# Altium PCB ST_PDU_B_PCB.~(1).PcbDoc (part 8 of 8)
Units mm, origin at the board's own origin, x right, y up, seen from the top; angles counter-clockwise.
Board outline 200 x 200 mm, 6 copper layers (Top Layer, Layer 1, Layer 2, Layer 3, Layer 4, Bottom Layer), stack 3.194 mm thick; 894 components, 723 nets, 3233 pads, 4067 vias.
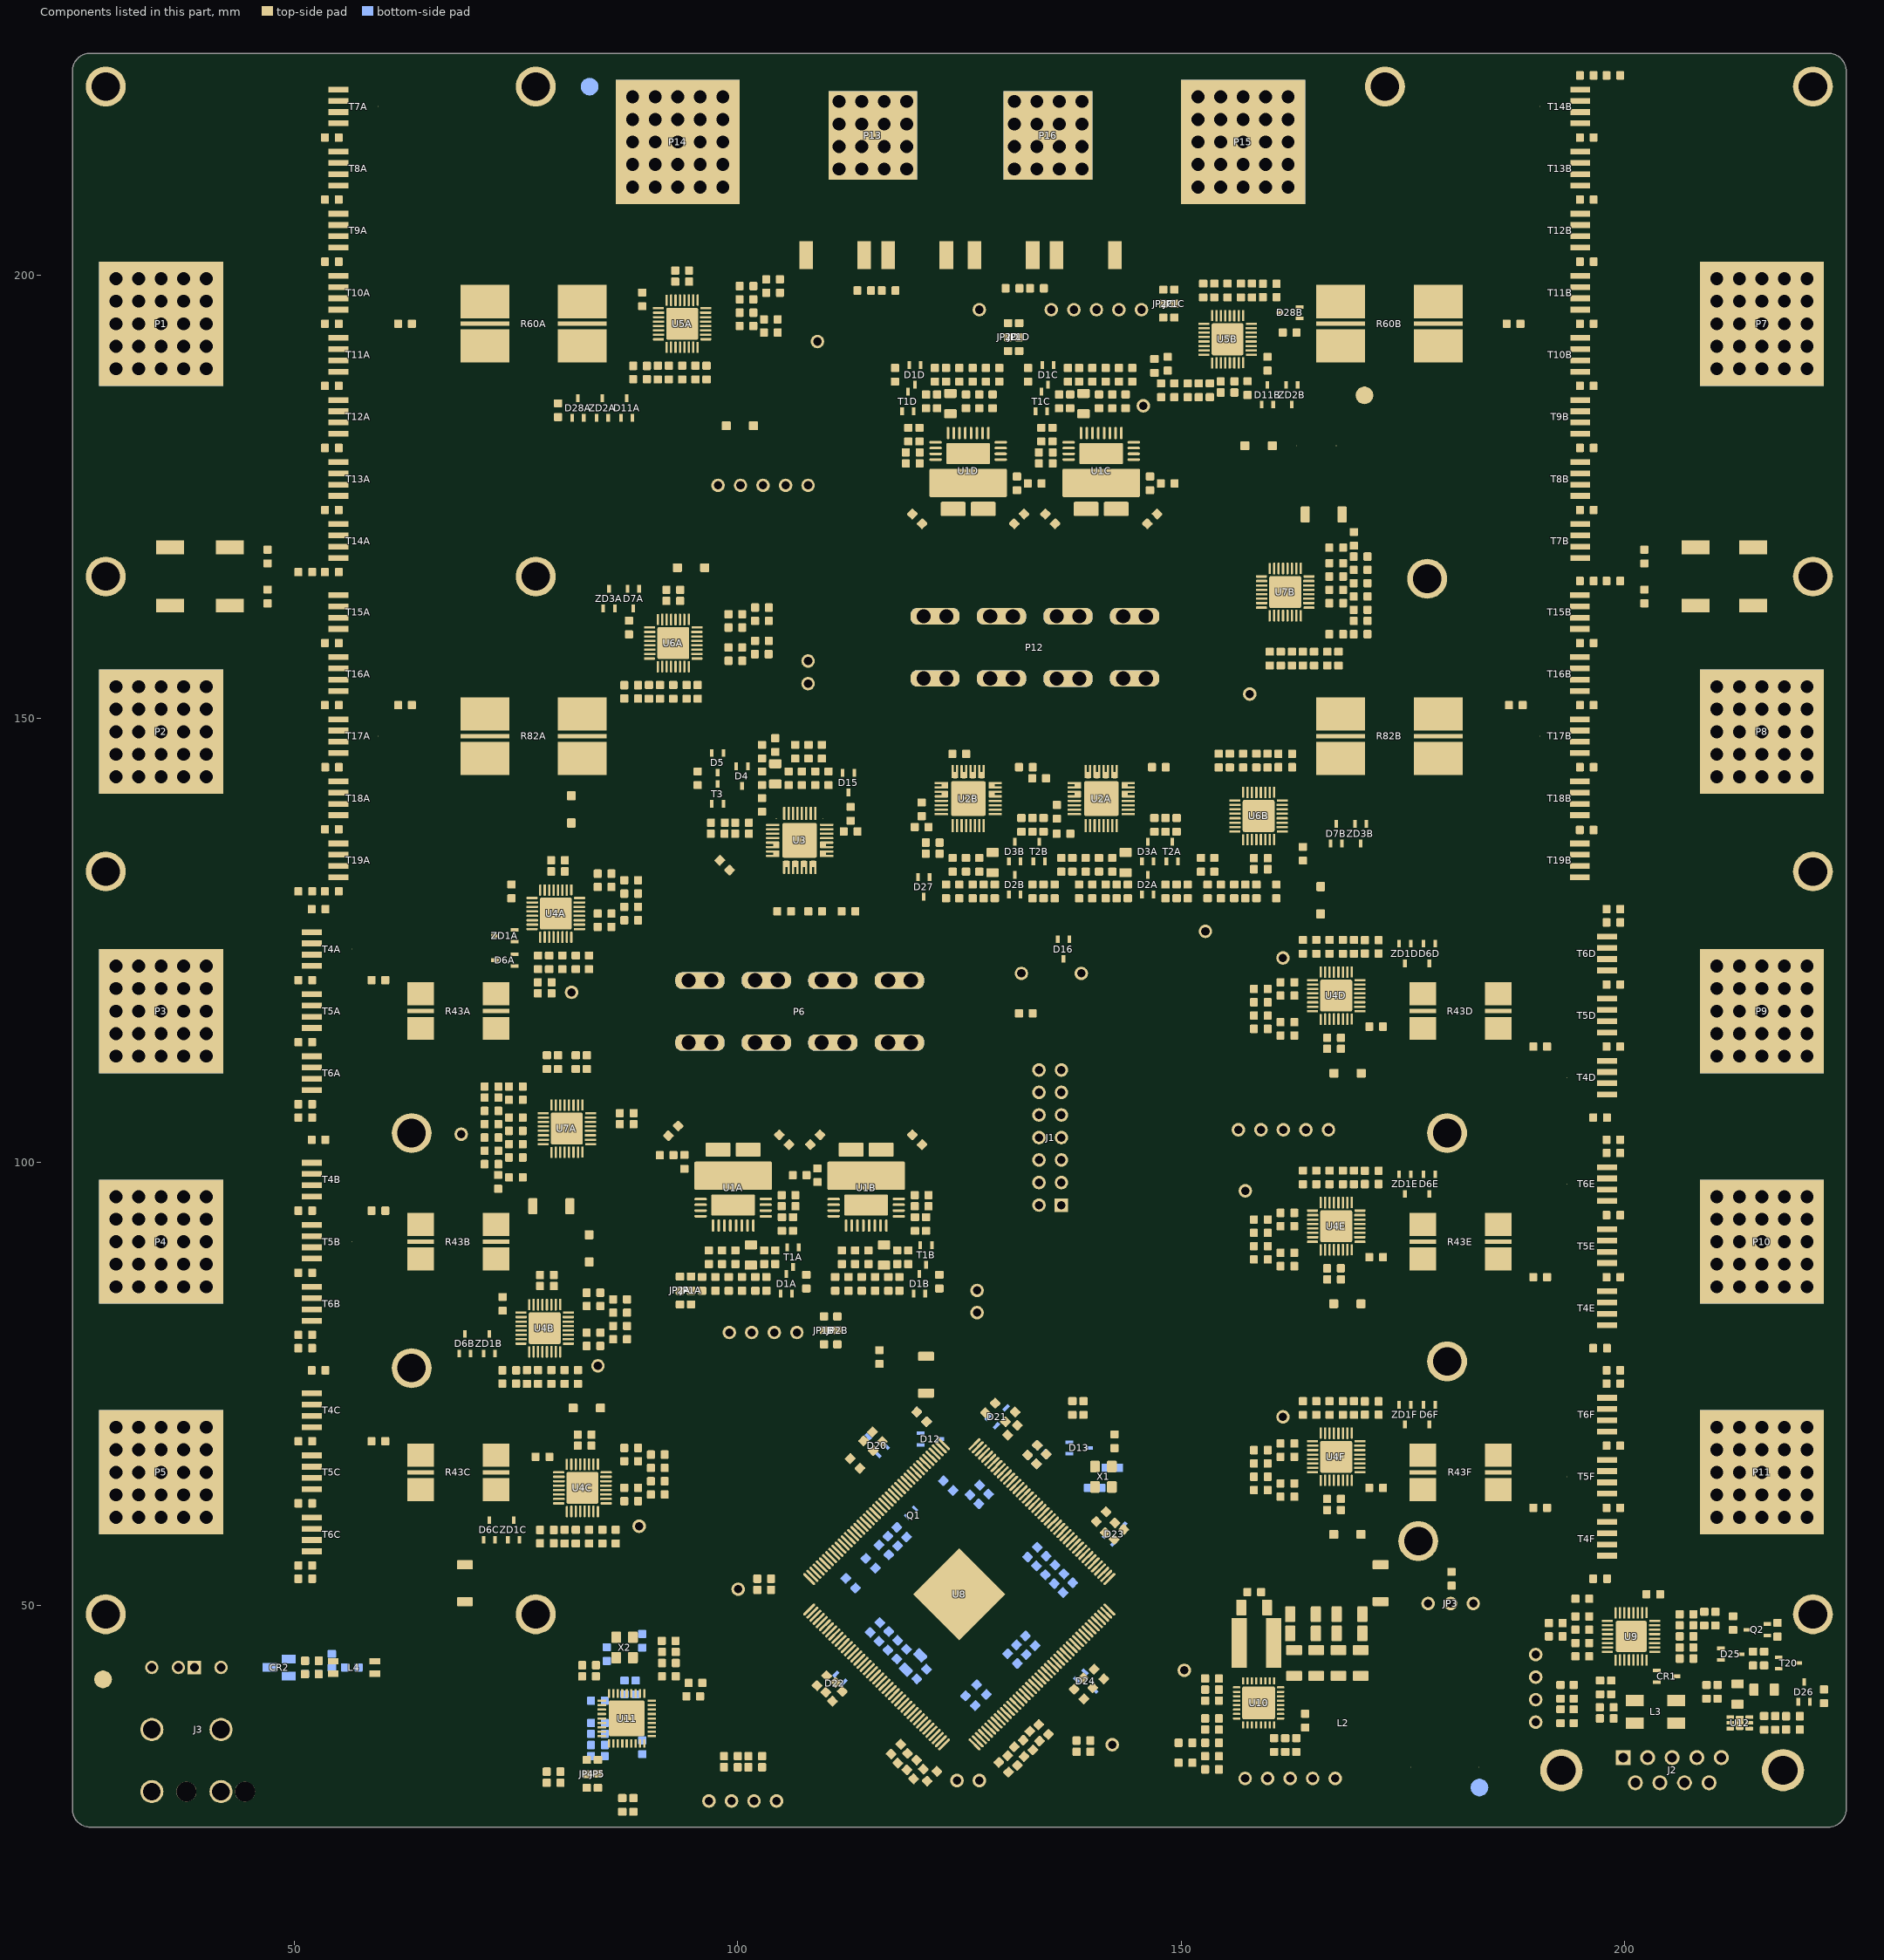
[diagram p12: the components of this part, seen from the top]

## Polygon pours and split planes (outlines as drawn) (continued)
NetR43E_1 on Layer 1 "NETR43E_1_L02_P333" (solid, pour order 333): 196,101 184.5,101 181.5,98 181.5,83 184.5,80 196,80
NetR43D_1 on Layer 1 "NETR43D_1_L02_P321" (solid, pour order 321): 196,127 184.5,127 181.5,124 181.5,109 184.5,106 196,106
OUT_B3 on Layer 1 "OUT_B3_L02_P320" (solid, pour order 320): 198.75,104 225,104 225,129 198.75,129 196.75,127 196.75,106
NetR82A_1 on Layer 1 "NETR82A_1_L02_P008" (solid, pour order 8): 57,130.5 69.5,130.5 77,138 77,158 69.5,165.5 57,165.5
NetR60B_1 on Layer 1 "NETR60B_1_L02_P024" (solid, pour order 24): 193,166.5 181.5,166.5 173,175 173,215 180.5,222.5 193,222.5
OUT_A5 on Layer 1 "OUT_A5_L02_P308" (solid, pour order 308): 51.25,52.5 25,52.5 25,77.5 51.25,77.5 53.25,75.5 53.25,54.5
NetR60A_1 on Layer 1 "NETR60A_1_L02_P004" (solid, pour order 4): 57,166.5 69.5,166.5 77,174 77,215 69.5,222.5 57,222.5
OUT_A1 on Layer 1 "OUT_A1_L02_P003" (solid, pour order 3): 56,222.5 25,222.5 25,166.5 56,166.5
OUT_A2 on Layer 1 "OUT_A2_L02_P021" (solid, pour order 21): 56,130.5 25,130.5 25,165.5 56,165.5
OUT_A3 on Layer 1 "OUT_A3_L02_P022" (solid, pour order 22): 51.25,104.5 25,104.5 25,129.5 51.25,129.5 53.25,127.5 53.25,106.5
GND on Top Layer "Top Layer-GND" (solid, remove dead copper, pour order 574): 225,48 225,223 ccw(c223,223) 223,225 115,225 100.25,225 27,225 ccw(c27,223) 25,223 25,27 ccw(c27,27) 27,25 223,25 ccw(c223,27) 225,27
NetR43F_1 on Top Layer "NETR43F_1_L01_P360" (solid, pour order 360): 196,75 184.5,75 181.5,72 181.5,57 184.5,54 196,54
OUT_B5 on Top Layer "OUT_B5_L01_P359" (solid, pour order 359): 198.75,52 225,52 225,77 198.75,77 196.75,75 196.75,54
NetR43E_1 on Top Layer "NETR43E_1_L01_P347" (solid, pour order 347): 196,101 184.5,101 181.5,98 181.5,83 184.5,80 196,80
OUT_B4 on Top Layer "OUT_B4_L01_P346" (solid, pour order 346): 198.75,78 225,78 225,103 198.75,103 196.75,101 196.75,80
NetR43D_1 on Top Layer "NETR43D_1_L01_P335" (solid, pour order 335): 196,127 184.5,127 181.5,124 181.5,109 184.5,106 196,106
OUT_B3 on Top Layer "OUT_B3_L01_P334" (solid, pour order 334): 198.75,104 225,104 225,129 198.75,129 196.75,127 196.75,106
NetR43C_1 on Top Layer "NETR43C_1_L01_P323" (solid, pour order 323): 54,75.5 65.5,75.5 68.5,72.5 68.5,57.5 65.5,54.5 54,54.5
OUT_A5 on Top Layer "OUT_A5_L01_P322" (solid, pour order 322): 51.25,52.5 25,52.5 25,77.5 51.25,77.5 53.25,75.5 53.25,54.5
NetR43B_1 on Top Layer "NETR43B_1_L01_P311" (solid, pour order 311): 54.175,101.575 65.675,101.575 68.675,98.575 68.675,83.575 65.675,80.575 54.175,80.575
OUT_A4 on Top Layer "OUT_A4_L01_P310" (solid, pour order 310): 51.25,78.5 25,78.5 25,103.5 51.25,103.5 53.25,101.5 53.25,80.5
NetR60B_1 on Top Layer "NETR60B_1_L01_P280" (solid, pour order 280): 193,166.5 180.5,166.5 173,174 173,215 180.5,222.5 193,222.5
OUT_B1 on Top Layer "OUT_B1_L01_P279" (solid, pour order 279): 194,222.5 225,222.5 225,166.5 194,166.5
NetR43A_1 on Top Layer "NETR43A_1_L01_P271" (solid, pour order 271): 54,127.5 65.5,127.5 68.5,124.5 68.5,109.5 65.5,106.5 54,106.5
OUT_B2 on Top Layer "OUT_B2_L01_P257" (solid, pour order 257): 194,130.5 225,130.5 225,165.5 194,165.5
NetR82B_1 on Top Layer "NETR82B_1_L01_P226" (solid, pour order 226): 193,130.5 180.5,130.5 173,138 173,158 180.5,165.5 193,165.5
OUT_A3 on Top Layer "OUT_A3_L01_P185" (solid, pour order 185): 51.25,104.5 25,104.5 25,129.5 51.25,129.5 53.25,127.5 53.25,106.5
OUT_A2 on Top Layer "OUT_A2_L01_P173" (solid, pour order 173): 56,130.5 25,130.5 25,165.5 56,165.5
NetR82A_1 on Top Layer "NETR82A_1_L01_P168" (solid, pour order 168): 57,130.5 69.5,130.5 77,138 77,158 69.5,165.5 57,165.5
NetR60A_1 on Top Layer "NETR60A_1_L01_P167" (solid, pour order 167): 57,166.5 69.5,166.5 77,174 77,215 69.5,222.5 57,222.5
OUT_A1 on Top Layer "OUT_A1_L01_P163" (solid, pour order 163): 56,222.5 25,222.5 25,166.5 56,166.5
VCC on Top Layer "VCC_L01_P159" (solid, pour order 159): 160.75,40.5 166.25,40.5 166.25,42.75 161.75,42.75 161.75,42 160.75,41
VCCB on Top Layer "VCCB_L01_P573" (solid, pour order 573): 175,64.4 178.75,64.4 178.75,61.1 175,61.1
VCCB on Top Layer "VCCB_L01_P570" (solid, pour order 570): 175,68.9 178.75,68.9 178.75,65.6 175,65.6
VCCB on Top Layer "VCCB_L01_P569" (solid, pour order 569): 175,90.4 178.75,90.4 178.75,87.1 175,87.1
VCCB on Top Layer "VCCB_L01_P566" (solid, pour order 566): 175,94.9 178.75,94.9 178.75,91.6 175,91.6
VCCB on Top Layer "VCCB_L01_P565" (solid, pour order 565): 175,116.4 178.75,116.4 178.75,113.1 175,113.1
VCCB on Top Layer "VCCB_L01_P559" (solid, pour order 559): 175,120.9 178.75,120.9 178.75,117.6 175,117.6
VCCA on Top Layer "VCCA_L01_P557" (solid, pour order 557): 75,65.6 71.25,65.6 71.25,68.9 75,68.9
VCCA on Top Layer "VCCA_L01_P554" (solid, pour order 554): 75,61.1 71.25,61.1 71.25,64.4 75,64.4
VCCA on Top Layer "VCCA_L01_P553" (solid, pour order 553): 75,91.6 71.25,91.6 71.25,94.9 75,94.9
VCCA on Top Layer "VCCA_L01_P549" (solid, pour order 549): 75,87.1 71.25,87.1 71.25,90.4 75,90.4
VCCA on Top Layer "VCCA_L01_P548" (solid, pour order 548): 75,117.6 71.25,117.6 71.25,120.9 75,120.9
VCCA on Top Layer "VCCA_L01_P545" (solid, pour order 545): 75,113.1 71.25,113.1 71.25,116.4 75,116.4
OUT_A7 on Top Layer "OUT_A7_L01_P544" (solid, pour order 544): 99.75,100.5 99.75,114.5 106.5,114.5 106.5,103.75 103.25,100.5
OUT_A6 on Top Layer "OUT_A6_L01_P541" (solid, pour order 541): 99.25,100.5 99.25,114.5 92.5,114.5 92.5,103.75 95.75,100.5
NetTr_d18_A on Top Layer "NONET_L02_P-001" (solid, pour order 361): 113.5,204 117.75,204 117.75,200.5 113.5,200.5
NetTr_d19_A on Top Layer "NONET_L02_P-001" (solid, pour order 366): 132.5,204 136.75,204 136.75,200.5 132.5,200.5
VCCA on Top Layer "VCCA_L01_P539" (solid, pour order 539): 108.5,204 105.75,204 105.75,200.5 108.5,200.5
VCCB on Top Layer "VCCB_L01_P540" (solid, pour order 540): 141.75,204 144.5,204 144.5,200.5 141.75,200.5
VCCA on Top Layer "VCCA_L01_P538" (solid, pour order 538): 79.75,199.75 79.75,195 86,195 86,199.75
VCCA on Top Layer "VCCA_L01_P537" (solid, pour order 537): 79.75,189.25 79.75,194 86,194 86,189.25
VCCB on Top Layer "VCCB_L01_P158" (solid, pour order 158): 164.5,199.75 164.5,195 170.75,195 170.75,199.75
VCCB on Top Layer "NONET_L02_P-001" (solid, pour order 157): 164.5,189.25 164.5,194 170.75,194 170.75,189.25
OUT_B9 on Top Layer "OUT_B9_L01_P536" (solid, pour order 536): 125.75,174.5 125.75,160.5 119,160.5 119,171.25 122.25,174.5
OUT_B8 on Top Layer "OUT_B8_L01_P535" (solid, pour order 535): 126.25,174.5 126.25,160.5 133,160.5 133,171.25 129.75,174.5
OUT_B7 on Top Layer "OUT_B7_L01_P368" (solid, pour order 368): 140.75,174.5 140.75,160.5 134,160.5 134,171.25 137.25,174.5
OUT_B6 on Top Layer "OUT_B6_L01_P367" (solid, pour order 367): 141.25,174.5 141.25,160.5 148,160.5 148,171.25 144.75,174.5
3V3 on Top Layer "NONET_L02_P-001" (solid, pour order 160): 156.5,52.25 158,52.25 158,43.5 158.75,42.75 158.75,41.25 156.75,41.25 154.75,43.25 154.75,50.5
OUT_B13 on Top Layer "OUT_B13_L01_P294" (solid, pour order 294): 125,155.5 125,146.25 123.75,145 123.75,141 121.5,141 119.5,143 119.5,155.5
OUT_B10 on Top Layer "OUT_B10_L01_P298" (solid, pour order 298): 142,155.5 142,146.25 143.25,145 143.25,141 145.5,141 147.5,143 147.5,155.5
OUT_B11 on Top Layer "OUT_B11_L01_P299" (solid, pour order 299): 140,155.5 140,146.25 138.75,145 138.75,141 136.5,141 134.5,143 134.5,155.5
OUT_B12 on Top Layer "OUT_B12_L01_P295" (solid, pour order 295): 127,155.5 127,146.25 128.25,145 128.25,141 130.5,141 132.5,143 132.5,155.5
OUT_A9 on Top Layer "OUT_A9_L01_P293" (solid, pour order 293): 114.75,100.5 114.75,114.5 121.5,114.5 121.5,103.75 118.25,100.5
OUT_A8 on Top Layer "OUT_A8_L01_P292" (solid, pour order 292): 114.25,100.5 114.25,114.5 107.5,114.5 107.5,103.75 110.75,100.5
GND on Layer 2 "GND_L03_P603" (solid, pour order 603): 115,75.25 115,225 135,225 135,75.25
VCCB on Layer 2 "VCCB_L03_P598" (solid, remove dead copper, pour order 598): 135,194.5 123.25,182.75 123.25,138 135,126.25 135,76.5 159,52.5 225,52.5 225,223 ccw(c223,223) 223,225 135,225
GND on Layer 2 "GND_L03_P001" (solid, pour order 1): 157,137.25 157,140.75 160.5,140.75 160.5,137.25
VCC_EXT on Layer 2 "VCC_EXT_L03_P197" (solid, pour order 197): 120.25,220.75 120.25,210.75 110.25,210.75 110.25,220.75
GND on Layer 2 "GND_L03_P198" (solid, pour order 198): 130,220.75 130,210.75 140,210.75 140,220.75
GND on Layer 2 "GND_L03_P199" (solid, pour order 199): 165.75,91 165.75,94.5 169.25,94.5 169.25,91
GND on Layer 2 "GND_L03_P200" (solid, pour order 200): 199,48.25 202.5,48.25 202.5,44.75 199,44.75
GND on Layer 2 "GND_L03_P213" (solid, pour order 213): 120.25,51.25 125,56 129.75,51.25 125,46.5
OUT_B1 on Layer 2 "OUT_B1_L03_P223" (solid, pour order 223): 194,222.5 225,222.5 225,166.5 194,166.5
OUT_A1 on Layer 2 "OUT_A1_L03_P227" (solid, pour order 227): 56,222.5 25,222.5 25,166.5 56,166.5
NetR60A_1 on Layer 2 "NETR60A_1_L03_P228" (solid, pour order 228): 57,166.5 69.5,166.5 77,174 77,215 69.5,222.5 57,222.5
NetR82A_1 on Layer 2 "NETR82A_1_L03_P246" (solid, pour order 246): 57,130.5 69.5,130.5 77,138 77,158 69.5,165.5 57,165.5
OUT_A2 on Layer 2 "OUT_A2_L03_P263" (solid, pour order 263): 56,130.5 25,130.5 25,165.5 56,165.5
NetR43A_1 on Layer 2 "NETR43A_1_L03_P264" (solid, pour order 264): 54,127.5 65.5,127.5 68.5,124.5 68.5,109.5 65.5,106.5 54,106.5
OUT_A3 on Layer 2 "OUT_A3_L03_P277" (solid, pour order 277): 51.25,104.5 25,104.5 25,129.5 51.25,129.5 53.25,127.5 53.25,106.5
NetR82B_1 on Layer 2 "NETR82B_1_L03_P303" (solid, pour order 303): 193,130.5 180.5,130.5 173,138 173,158 180.5,165.5 193,165.5
OUT_B2 on Layer 2 "OUT_B2_L03_P304" (solid, pour order 304): 194,130.5 225,130.5 225,165.5 194,165.5
NetR60B_1 on Layer 2 "NETR60B_1_L03_P315" (solid, pour order 315): 193,166.5 180.5,166.5 173,174 173,215 180.5,222.5 193,222.5
NetR43B_1 on Layer 2 "NETR43B_1_L03_P316" (solid, pour order 316): 54.175,101.575 65.675,101.575 68.675,98.575 68.675,83.575 65.675,80.575 54.175,80.575
OUT_A4 on Layer 2 "OUT_A4_L03_P327" (solid, pour order 327): 51.25,78.5 25,78.5 25,103.5 51.25,103.5 53.25,101.5 53.25,80.5
NetR43C_1 on Layer 2 "NETR43C_1_L03_P328" (solid, pour order 328): 54,75.5 65.5,75.5 68.5,72.5 68.5,57.5 65.5,54.5 54,54.5
OUT_A5 on Layer 2 "OUT_A5_L03_P339" (solid, pour order 339): 51.25,52.5 25,52.5 25,77.5 51.25,77.5 53.25,75.5 53.25,54.5
NetR43D_1 on Layer 2 "NETR43D_1_L03_P340" (solid, pour order 340): 196,127 184.5,127 181.5,124 181.5,109 184.5,106 196,106
OUT_B3 on Layer 2 "OUT_B3_L03_P351" (solid, pour order 351): 198.75,104 225,104 225,129 198.75,129 196.75,127 196.75,106
NetR43E_1 on Layer 2 "NETR43E_1_L03_P352" (solid, pour order 352): 196,101 184.5,101 181.5,98 181.5,83 184.5,80 196,80
OUT_B4 on Layer 2 "OUT_B4_L03_P371" (solid, pour order 371): 198.75,78 225,78 225,103 198.75,103 196.75,101 196.75,80
NetR43F_1 on Layer 2 "NETR43F_1_L03_P372" (solid, pour order 372): 196,75 184.5,75 181.5,72 181.5,57 184.5,54 196,54
OUT_B5 on Layer 2 "OUT_B5_L03_P373" (solid, pour order 373): 198.75,52 225,52 225,77 198.75,77 196.75,75 196.75,54
GND on Layer 2 "GND_L03_P379" (solid, pour order 379): 165.75,65 165.75,68.5 169.25,68.5 169.25,65
GND on Layer 2 "GND_L03_P384" (solid, pour order 384): 199,44.75 199,48.25 202.5,48.25 202.5,44.75
GND on Layer 2 "GND_L03_P389" (solid, pour order 389): 165.75,117 165.75,120.5 169.25,120.5 169.25,117
GND on Layer 2 "GND_L03_P394" (solid, pour order 394): 160,162.5 160,166 163.5,166 163.5,162.5
GND on Layer 2 "GND_L03_P399" (solid, pour order 399): 153.5,191 153.5,194.5 157,194.5 157,191
GND on Layer 2 "GND_L03_P404" (solid, pour order 404): 92,192.75 92,196.25 95.5,196.25 95.5,192.75
GND on Layer 2 "GND_L03_P409" (solid, pour order 409): 91,156.75 91,160.25 94.5,160.25 94.5,156.75
GND on Layer 2 "GND_L03_P414" (solid, pour order 414): 77.75,126.25 77.75,129.75 81.25,129.75 81.25,126.25
GND on Layer 2 "GND_L03_P419" (solid, pour order 419): 79,102 79,105.5 82.5,105.5 82.5,102
GND on Layer 2 "GND_L03_P424" (solid, pour order 424): 76.5,79.5 76.5,83 80,83 80,79.5
GND on Layer 2 "GND_L03_P429" (solid, pour order 429): 80.75,61.5 80.75,65 84.25,65 84.25,61.5
GND on Layer 2 "GND_L03_P434" (solid, pour order 434): 85.75,35.5 85.75,39 89.25,39 89.25,35.5
GND on Layer 2 "GND_L03_P439" (solid, pour order 439): 157,37.25 157,40.75 160.5,40.75 160.5,37.25
VCCA on Layer 2 "VCCA_L03_P448" (solid, pour order 448): 105,134.25 105,138.25 109,138.25 109,134.25
VCCB on Layer 2 "VCCB_L03_P453" (solid, pour order 453): 124,139 124,143 128,143 128,139
VCCB on Layer 2 "VCCB_L03_P458" (solid, pour order 458): 139,139 139,143 143,143 143,139
OUT_B12 on Layer 2 "NONET_L02_P-001" (solid, pour order 460): 129,141 129,143.5 131.5,143.5 131.5,142 130.5,141
OUT_B10 on Layer 2 "NONET_L02_P-001" (solid, pour order 464): 144,141 144,143.5 146.5,143.5 146.5,142 145.5,141
OUT_B11 on Layer 2 "NONET_L02_P-001" (solid, pour order 468): 138,141 138,143.5 135.5,143.5 135.5,142 136.5,141
OUT_B13 on Layer 2 "NONET_L02_P-001" (solid, pour order 472): 123,141 123,143.5 120.5,143.5 120.5,142 121.5,141
VCCB on Layer 2 "VCCB_L03_P480" (solid, pour order 480): 122.5,175 122.5,178.25 129.5,178.25 129.5,175
OUT_B9 on Layer 2 "OUT_B9_L03_P481" (solid, pour order 481): 125.75,172 121.75,172 121.75,173.75 122.5,174.5 125.75,174.5
OUT_B8 on Layer 2 "OUT_B8_L03_P491" (solid, pour order 491): 126.25,172 130.25,172 130.25,173.75 129.5,174.5 126.25,174.5
VCCB on Layer 2 "VCCB_L03_P499" (solid, pour order 499): 137.5,175 137.5,178.25 144.5,178.25 144.5,175
OUT_B7 on Layer 2 "OUT_B7_L03_P500" (solid, pour order 500): 140.75,172 136.75,172 136.75,173.75 137.5,174.5 140.75,174.5
OUT_B6 on Layer 2 "OUT_B6_L03_P504" (solid, pour order 504): 141.25,172 145.25,172 145.25,173.75 144.5,174.5 141.25,174.5
VCCA on Layer 2 "VCCA_L03_P512" (solid, pour order 512): 118,100 118,96.75 111,96.75 111,100
OUT_A9 on Layer 2 "OUT_A9_L03_P513" (solid, pour order 513): 114.75,103 118.75,103 118.75,101.25 118,100.5 114.75,100.5
OUT_A8 on Layer 2 "OUT_A8_L03_P517" (solid, pour order 517): 114.25,103 110.25,103 110.25,101.25 111,100.5 114.25,100.5
VCCA on Layer 2 "VCCA_L03_P525" (solid, pour order 525): 103,100 103,96.75 96,96.75 96,100
OUT_A7 on Layer 2 "OUT_A7_L03_P526" (solid, pour order 526): 99.75,103 103.75,103 103.75,101.25 103,100.5 99.75,100.5
OUT_A6 on Layer 2 "OUT_A6_L03_P530" (solid, pour order 530): 99.25,103 95.25,103 95.25,101.25 96,100.5 99.25,100.5
VCCA on Layer 2 "VCCA_L03_P587" (solid, pour order 587): 115,110.25 121.5,103.75 121.5,96 115,89.5 115,76.5 91,52.5 25,52.5 25,223 cw(c27,223) 27,225 115,225 115,130.75
VCC on Layer 2 "VCC_L03_P599" (solid, pour order 599): 91.5,52 116,76.5 134,76.5 158.5,52 225,52 225,27 cw(c223,27) 223,25 27,25 cw(c27,27) 25,27 25,52
GND on Layer 3 "GND_L04_P601" (solid, pour order 601): 25,27 25,223 cw(c27,223) 27,225 223,225 cw(c223,223) 225,223 225,27 cw(c223,27) 223,25 27,25 cw(c27,27)
OUT_B1 on Layer 3 "OUT_B1_L04_P205" (solid, pour order 205): 194,222.5 225,222.5 225,166.5 194,166.5
VCCA on Layer 3 "NONET_L02_P-001" (solid, pour order 605): 75.2,65.7 70.95,65.7 70.95,68.95 75.2,68.95
VCCB on Layer 3 "VCCB_L04_P600" (solid, pour order 600): 150,222 164,222 164,208 150,208
VCCA on Layer 3 "VCCA_L04_P596" (solid, pour order 596): 86.25,222 100.25,222 100.25,208 86.25,208
VCC_EXT on Layer 3 "VCC_EXT_L04_P586" (solid, pour order 586): 120.25,220.75 120.25,210.75 110.25,210.75 110.25,220.75
VCCB on Layer 3 "VCCB_L04_P585" (solid, pour order 585): 165.25,143.5 165.25,147.5 170.75,147.5 170.75,143.5
VCCB on Layer 3 "VCCB_L04_P584" (solid, pour order 584): 170.75,148.5 170.75,152.5 165.25,152.5 165.25,148.5
VCCA on Layer 3 "VCCA_L04_P583" (solid, pour order 583): 79.75,143.5 79.75,147.5 85.25,147.5 85.25,143.5
VCCA on Layer 3 "VCCA_L04_P582" (solid, pour order 582): 79.75,152.5 79.75,148.5 85.25,148.5 85.25,152.5
VCCB on Layer 3 "VCCB_L04_P581" (solid, pour order 581): 164.5,194 170.75,194 170.75,189.25 164.5,189.25
VCCB on Layer 3 "VCCB_L04_P578" (solid, pour order 578): 164.5,199.75 170.75,199.75 170.75,195 164.5,195
VCCA on Layer 3 "VCCA_L04_P577" (solid, pour order 577): 79.75,194 86,194 86,189.25 79.75,189.25
VCCA on Layer 3 "VCCA_L04_P576" (solid, pour order 576): 79.75,199.75 86,199.75 86,195 79.75,195
VCCB on Layer 3 "NONET_L02_P-001" (solid, pour order 575): 174.8,64.3 179.05,64.3 179.05,61.05 174.8,61.05
VCCB on Layer 3 "NONET_L02_P-001" (solid, pour order 572): 174.75,69 179,69 179,65.75 174.75,65.75
VCCB on Layer 3 "NONET_L02_P-001" (solid, pour order 571): 174.8,90.3 179.05,90.3 179.05,87.05 174.8,87.05
VCCB on Layer 3 "NONET_L02_P-001" (solid, pour order 568): 174.75,95 179,95 179,91.75 174.75,91.75
VCCB on Layer 3 "NONET_L02_P-001" (solid, pour order 567): 174.8,116.3 179.05,116.3 179.05,113.05 174.8,113.05
VCCB on Layer 3 "NONET_L02_P-001" (solid, pour order 560): 174.75,121 179,121 179,117.75 174.75,117.75
VCCA on Layer 3 "NONET_L02_P-001" (solid, pour order 556): 75.25,61 71,61 71,64.25 75.25,64.25
VCCA on Layer 3 "NONET_L02_P-001" (solid, pour order 555): 75.2,91.7 70.95,91.7 70.95,94.95 75.2,94.95
VCCA on Layer 3 "NONET_L02_P-001" (solid, pour order 552): 75.25,87 71,87 71,90.25 75.25,90.25
VCCA on Layer 3 "NONET_L02_P-001" (solid, pour order 550): 75.2,117.7 70.95,117.7 70.95,120.95 75.2,120.95
VCCA on Layer 3 "NONET_L02_P-001" (solid, pour order 533): 75.25,113 71,113 71,116.25 75.25,116.25
OUT_A6 on Layer 3 "OUT_A6_L04_P529" (solid, pour order 529): 99.25,103 95.25,103 95.25,101.25 96,100.5 99.25,100.5
OUT_A7 on Layer 3 "OUT_A7_L04_P523" (solid, pour order 523): 99.75,103 103.75,103 103.75,101.25 103,100.5 99.75,100.5
VCCA on Layer 3 "VCCA_L04_P520" (solid, pour order 520): 103,100 103,96.75 96,96.75 96,100
OUT_A8 on Layer 3 "OUT_A8_L04_P516" (solid, pour order 516): 114.25,103 110.25,103 110.25,101.25 111,100.5 114.25,100.5
OUT_A9 on Layer 3 "OUT_A9_L04_P510" (solid, pour order 510): 114.75,103 118.75,103 118.75,101.25 118,100.5 114.75,100.5
VCCA on Layer 3 "VCCA_L04_P507" (solid, pour order 507): 118,100 118,96.75 111,96.75 111,100
OUT_B6 on Layer 3 "OUT_B6_L04_P503" (solid, pour order 503): 141.25,172 145.25,172 145.25,173.75 144.5,174.5 141.25,174.5
OUT_B7 on Layer 3 "OUT_B7_L04_P497" (solid, pour order 497): 140.75,172 136.75,172 136.75,173.75 137.5,174.5 140.75,174.5
VCCB on Layer 3 "VCCB_L04_P494" (solid, pour order 494): 137.5,175 137.5,178.25 144.5,178.25 144.5,175
OUT_B8 on Layer 3 "OUT_B8_L04_P489" (solid, pour order 489): 126.25,172 130.25,172 130.25,173.75 129.5,174.5 126.25,174.5
OUT_B9 on Layer 3 "OUT_B9_L04_P478" (solid, pour order 478): 125.75,172 121.75,172 121.75,173.75 122.5,174.5 125.75,174.5
VCCB on Layer 3 "VCCB_L04_P473" (solid, pour order 473): 122.5,175 122.5,178.25 129.5,178.25 129.5,175
OUT_B13 on Layer 3 "OUT_B13_L04_P469" (solid, pour order 469): 123,141 123,143.5 120.5,143.5 120.5,142 121.5,141
OUT_B11 on Layer 3 "OUT_B11_L04_P465" (solid, pour order 465): 138,141 138,143.5 135.5,143.5 135.5,142 136.5,141
OUT_B10 on Layer 3 "OUT_B10_L04_P461" (solid, pour order 461): 144,141 144,143.5 146.5,143.5 146.5,142 145.5,141
OUT_B12 on Layer 3 "OUT_B12_L04_P455" (solid, pour order 455): 129,141 129,143.5 131.5,143.5 131.5,142 130.5,141
VCCB on Layer 3 "VCCB_L04_P450" (solid, pour order 450): 139,139 139,143 143,143 143,139
VCCB on Layer 3 "VCCB_L04_P444" (solid, pour order 444): 124,139 124,143 128,143 128,139
VCCA on Layer 3 "VCCA_L04_P442" (solid, pour order 442): 105,134.25 105,138.25 109,138.25 109,134.25
GND on Layer 3 "GND_L04_P437" (solid, pour order 437): 157,37.25 157,40.75 160.5,40.75 160.5,37.25
GND on Layer 3 "GND_L04_P432" (solid, pour order 432): 85.75,35.5 85.75,39 89.25,39 89.25,35.5
GND on Layer 3 "GND_L04_P427" (solid, pour order 427): 80.75,61.5 80.75,65 84.25,65 84.25,61.5
GND on Layer 3 "GND_L04_P422" (solid, pour order 422): 76.5,79.5 76.5,83 80,83 80,79.5
GND on Layer 3 "GND_L04_P417" (solid, pour order 417): 79,102 79,105.5 82.5,105.5 82.5,102
GND on Layer 3 "GND_L04_P412" (solid, pour order 412): 77.75,126.25 77.75,129.75 81.25,129.75 81.25,126.25
GND on Layer 3 "GND_L04_P407" (solid, pour order 407): 91,156.75 91,160.25 94.5,160.25 94.5,156.75
GND on Layer 3 "GND_L04_P402" (solid, pour order 402): 92,192.75 92,196.25 95.5,196.25 95.5,192.75
GND on Layer 3 "GND_L04_P397" (solid, pour order 397): 153.5,191 153.5,194.5 157,194.5 157,191
GND on Layer 3 "GND_L04_P387" (solid, pour order 387): 165.75,117 165.75,120.5 169.25,120.5 169.25,117
GND on Layer 3 "GND_L04_P382" (solid, pour order 382): 199,44.75 199,48.25 202.5,48.25 202.5,44.75
GND on Layer 3 "GND_L04_P377" (solid, pour order 377): 165.75,65 165.75,68.5 169.25,68.5 169.25,65
GND on Layer 3 "GND_L04_P354" (solid, pour order 354): 165.75,91 165.75,94.5 169.25,94.5 169.25,91
OUT_B2 on Layer 3 "OUT_B2_L04_P208" (solid, pour order 208): 194,130.5 225,130.5 225,165.5 194,165.5
NetR60B_1 on Layer 3 "NETR60B_1_L04_P166" (solid, pour order 166): 193,166.5 180.5,166.5 173,174 173,215 180.5,222.5 193,222.5
OUT_A2 on Layer 3 "OUT_A2_L04_P220" (solid, pour order 220): 56,130.5 25,130.5 25,165.5 56,165.5
NetR82A_1 on Layer 3 "NETR82A_1_L04_P219" (solid, pour order 219): 57,130.5 69.5,130.5 77,138 77,158 69.5,165.5 57,165.5
OUT_A1 on Layer 3 "OUT_A1_L04_P217" (solid, pour order 217): 56,222.5 25,222.5 25,166.5 56,166.5
NetR82B_1 on Layer 3 "NETR82B_1_L04_P247" (solid, pour order 247): 193,130.5 180.5,130.5 173,138 173,158 180.5,165.5 193,165.5
NetR43A_1 on Layer 3 "NETR43A_1_L04_P233" (solid, pour order 233): 54,127.5 65.5,127.5 68.5,124.5 68.5,109.5 65.5,106.5 54,106.5
OUT_B4 on Layer 3 "OUT_B4_L04_P341" (solid, pour order 341): 198.75,78 225,78 225,103 198.75,103 196.75,101 196.75,80
OUT_A4 on Layer 3 "OUT_A4_L04_P305" (solid, pour order 305): 51.25,78.5 25,78.5 25,103.5 51.25,103.5 53.25,101.5 53.25,80.5
NetR43B_1 on Layer 3 "NETR43B_1_L04_P267" (solid, pour order 267): 54.175,101.575 65.675,101.575 68.675,98.575 68.675,83.575 65.675,80.575 54.175,80.575
NetR43C_1 on Layer 3 "NETR43C_1_L04_P306" (solid, pour order 306): 54,75.5 65.5,75.5 68.5,72.5 68.5,57.5 65.5,54.5 54,54.5
OUT_B5 on Layer 3 "OUT_B5_L04_P353" (solid, pour order 353): 198.75,52 225,52 225,77 198.75,77 196.75,75 196.75,54
NetR43F_1 on Layer 3 "NETR43F_1_L04_P342" (solid, pour order 342): 196,75 184.5,75 181.5,72 181.5,57 184.5,54 196,54
NetR43E_1 on Layer 3 "NETR43E_1_L04_P330" (solid, pour order 330): 196,101 184.5,101 181.5,98 181.5,83 184.5,80 196,80
OUT_B3 on Layer 3 "OUT_B3_L04_P329" (solid, pour order 329): 198.75,104 225,104 225,129 198.75,129 196.75,127 196.75,106
NetR43D_1 on Layer 3 "NETR43D_1_L04_P318" (solid, pour order 318): 196,127 184.5,127 181.5,124 181.5,109 184.5,106 196,106
OUT_A5 on Layer 3 "OUT_A5_L04_P317" (solid, pour order 317): 51.25,52.5 25,52.5 25,77.5 51.25,77.5 53.25,75.5 53.25,54.5
NetR60A_1 on Layer 3 "NETR60A_1_L04_P218" (solid, pour order 218): 57,166.5 69.5,166.5 77,174 77,215 69.5,222.5 57,222.5
OUT_A3 on Layer 3 "OUT_A3_L04_P243" (solid, pour order 243): 51.25,104.5 25,104.5 25,129.5 51.25,129.5 53.25,127.5 53.25,106.5
GND on Layer 4 "GND_L05_P602" (solid, pour order 602): 115,75.25 115,225 135,225 135,75.25
VCCB on Layer 4 "VCCB_L05_P594" (solid, pour order 594): 135,194.5 123.25,182.75 123.25,138 135,126.25 135,76.5 159,52.5 225,52.5 225,223 ccw(c223,223) 223,225 135,225
VCCA on Layer 4 "VCCA_L05_P531" (solid, pour order 531): 115,89.5 121.5,96 121.5,103.75 115,110.25 115,225 27,225 ccw(c27,223) 25,223 25,52.5 91,52.5 115,76.5
3V3 on Layer 4 "3V3_L05_P595" (solid, pour order 595): 91.5,52 116,76.5 134,76.5 158.5,52 225,52 225,27 cw(c223,27) 223,25 27,25 cw(c27,27) 25,27 25,52
VCC_EXT on Layer 4 "VCC_EXT_L05_P165" (solid, pour order 165): 120.25,220.75 120.25,210.75 110.25,210.75 110.25,220.75
GND on Layer 4 "GND_L05_P177" (solid, pour order 177): 130,220.75 130,210.75 140,210.75 140,220.75
GND on Layer 4 "GND_L05_P588" (solid, pour order 588): 157,140.75 157,137.25 160.5,137.25 160.5,140.75
OUT_A6 on Layer 4 "OUT_A6_L05_P527" (solid, pour order 527): 99.25,103 95.25,103 95.25,101.25 96,100.5 99.25,100.5
OUT_A7 on Layer 4 "OUT_A7_L05_P524" (solid, pour order 524): 99.75,103 103.75,103 103.75,101.25 103,100.5 99.75,100.5
VCCA on Layer 4 "VCCA_L05_P518" (solid, pour order 518): 103,100 103,96.75 96,96.75 96,100
OUT_A8 on Layer 4 "OUT_A8_L05_P514" (solid, pour order 514): 114.25,103 110.25,103 110.25,101.25 111,100.5 114.25,100.5
OUT_A9 on Layer 4 "OUT_A9_L05_P511" (solid, pour order 511): 114.75,103 118.75,103 118.75,101.25 118,100.5 114.75,100.5
VCCA on Layer 4 "VCCA_L05_P505" (solid, pour order 505): 118,100 118,96.75 111,96.75 111,100
OUT_B6 on Layer 4 "OUT_B6_L05_P501" (solid, pour order 501): 141.25,172 145.25,172 145.25,173.75 144.5,174.5 141.25,174.5
OUT_B7 on Layer 4 "OUT_B7_L05_P498" (solid, pour order 498): 140.75,172 136.75,172 136.75,173.75 137.5,174.5 140.75,174.5
VCCB on Layer 4 "VCCB_L05_P492" (solid, pour order 492): 137.5,175 137.5,178.25 144.5,178.25 144.5,175
OUT_B8 on Layer 4 "OUT_B8_L05_P483" (solid, pour order 483): 126.25,172 130.25,172 130.25,173.75 129.5,174.5 126.25,174.5
OUT_B9 on Layer 4 "OUT_B9_L05_P479" (solid, pour order 479): 125.75,172 121.75,172 121.75,173.75 122.5,174.5 125.75,174.5
VCCB on Layer 4 "VCCB_L05_P474" (solid, pour order 474): 122.5,175 122.5,178.25 129.5,178.25 129.5,175
OUT_B13 on Layer 4 "OUT_B13_L05_P470" (solid, pour order 470): 123,141 123,143.5 120.5,143.5 120.5,142 121.5,141
OUT_B11 on Layer 4 "OUT_B11_L05_P466" (solid, pour order 466): 138,141 138,143.5 135.5,143.5 135.5,142 136.5,141
OUT_B10 on Layer 4 "OUT_B10_L05_P462" (solid, pour order 462): 144,141 144,143.5 146.5,143.5 146.5,142 145.5,141
OUT_B12 on Layer 4 "OUT_B12_L05_P457" (solid, pour order 457): 129,141 129,143.5 131.5,143.5 131.5,142 130.5,141
VCCB on Layer 4 "VCCB_L05_P452" (solid, pour order 452): 139,139 139,143 143,143 143,139
VCCB on Layer 4 "VCCB_L05_P447" (solid, pour order 447): 124,139 124,143 128,143 128,139
VCCA on Layer 4 "VCCA_L05_P441" (solid, pour order 441): 105,134.25 105,138.25 109,138.25 109,134.25
GND on Layer 4 "GND_L05_P436" (solid, pour order 436): 157,37.25 157,40.75 160.5,40.75 160.5,37.25
GND on Layer 4 "GND_L05_P431" (solid, pour order 431): 85.75,35.5 85.75,39 89.25,39 89.25,35.5
GND on Layer 4 "GND_L05_P426" (solid, pour order 426): 80.75,61.5 80.75,65 84.25,65 84.25,61.5
GND on Layer 4 "GND_L05_P421" (solid, pour order 421): 76.5,79.5 76.5,83 80,83 80,79.5
GND on Layer 4 "GND_L05_P416" (solid, pour order 416): 79,102 79,105.5 82.5,105.5 82.5,102
GND on Layer 4 "GND_L05_P411" (solid, pour order 411): 77.75,126.25 77.75,129.75 81.25,129.75 81.25,126.25
GND on Layer 4 "GND_L05_P406" (solid, pour order 406): 91,156.75 91,160.25 94.5,160.25 94.5,156.75
GND on Layer 4 "GND_L05_P401" (solid, pour order 401): 92,192.75 92,196.25 95.5,196.25 95.5,192.75
GND on Layer 4 "GND_L05_P396" (solid, pour order 396): 153.5,191 153.5,194.5 157,194.5 157,191
GND on Layer 4 "GND_L05_P391" (solid, pour order 391): 160,162.5 160,166 163.5,166 163.5,162.5
GND on Layer 4 "GND_L05_P386" (solid, pour order 386): 165.75,117 165.75,120.5 169.25,120.5 169.25,117
GND on Layer 4 "GND_L05_P381" (solid, pour order 381): 199,44.75 199,48.25 202.5,48.25 202.5,44.75
GND on Layer 4 "GND_L05_P376" (solid, pour order 376): 165.75,65 165.75,68.5 169.25,68.5 169.25,65
GND on Layer 4 "GND_L05_P349" (solid, pour order 349): 165.75,91 165.75,94.5 169.25,94.5 169.25,91
GND on Layer 4 "GND_L05_P178" (solid, pour order 178): 120.25,51.25 125,56 129.75,51.25 125,46.5
OUT_B2 on Layer 4 "OUT_B2_L05_P245" (solid, pour order 245): 194,130.5 225,130.5 225,165.5 194,165.5
OUT_B1 on Layer 4 "OUT_B1_L05_P262" (solid, pour order 262): 194,222.5 225,222.5 225,166.5 194,166.5
NetR60B_1 on Layer 4 "NETR60B_1_L05_P188" (solid, pour order 188): 193,166.5 180.5,166.5 173,174 173,215 180.5,222.5 193,222.5
OUT_A2 on Layer 4 "OUT_A2_L05_P186" (solid, pour order 186): 56,130.5 25,130.5 25,165.5 56,165.5
NetR82A_1 on Layer 4 "NETR82A_1_L05_P183" (solid, pour order 183): 57,130.5 69.5,130.5 77,138 77,158 69.5,165.5 57,165.5
NetR60A_1 on Layer 4 "NETR60A_1_L05_P180" (solid, pour order 180): 57,166.5 69.5,166.5 77,174 77,215 69.5,222.5 57,222.5
NetR82B_1 on Layer 4 "NETR82B_1_L05_P193" (solid, pour order 193): 193,130.5 180.5,130.5 173,138 173,158 180.5,165.5 193,165.5
NetR43A_1 on Layer 4 "NETR43A_1_L05_P261" (solid, pour order 261): 54,127.5 65.5,127.5 68.5,124.5 68.5,109.5 65.5,106.5 54,106.5
OUT_B4 on Layer 4 "OUT_B4_L05_P325" (solid, pour order 325): 198.75,78 225,78 225,103 198.75,103 196.75,101 196.75,80
NetR43B_1 on Layer 4 "NETR43B_1_L05_P300" (solid, pour order 300): 54.175,101.575 65.675,101.575 68.675,98.575 68.675,83.575 65.675,80.575 54.175,80.575
OUT_A4 on Layer 4 "OUT_A4_L05_P275" (solid, pour order 275): 51.25,78.5 25,78.5 25,103.5 51.25,103.5 53.25,101.5 53.25,80.5
NetR43C_1 on Layer 4 "NETR43C_1_L05_P312" (solid, pour order 312): 54,75.5 65.5,75.5 68.5,72.5 68.5,57.5 65.5,54.5 54,54.5
NetR43F_1 on Layer 4 "NETR43F_1_L05_P348" (solid, pour order 348): 196,75 184.5,75 181.5,72 181.5,57 184.5,54 196,54
OUT_B5 on Layer 4 "OUT_B5_L05_P337" (solid, pour order 337): 198.75,52 225,52 225,77 198.75,77 196.75,75 196.75,54
NetR43E_1 on Layer 4 "NETR43E_1_L05_P336" (solid, pour order 336): 196,101 184.5,101 181.5,98 181.5,83 184.5,80 196,80
NetR43D_1 on Layer 4 "NETR43D_1_L05_P324" (solid, pour order 324): 196,127 184.5,127 181.5,124 181.5,109 184.5,106 196,106
OUT_B3 on Layer 4 "OUT_B3_L05_P313" (solid, pour order 313): 198.75,104 225,104 225,129 198.75,129 196.75,127 196.75,106
OUT_A5 on Layer 4 "OUT_A5_L05_P301" (solid, pour order 301): 51.25,52.5 25,52.5 25,77.5 51.25,77.5 53.25,75.5 53.25,54.5
OUT_A1 on Layer 4 "OUT_A1_L05_P179" (solid, pour order 179): 56,222.5 25,222.5 25,166.5 56,166.5
OUT_A3 on Layer 4 "OUT_A3_L05_P187" (solid, pour order 187): 51.25,104.5 25,104.5 25,129.5 51.25,129.5 53.25,127.5 53.25,106.5
VCCA on Bottom Layer "VCCA_L06_P528" (solid, pour order 528): 115,140.25 115,130.75 115,76.5 91,52.5 25,52.5 25,223 cw(c27,223) 27,225 115,225
GND on Bottom Layer "Bottom Layer-GND" (solid, remove dead copper, pour order 532): 25,27 ccw(c27,27) 27,25 223,25 ccw(c223,27) 225,27 225,52 158.5,52 135,75.5 135,225 115,225 115,75.5 91.5,52 25,52
VCCB on Bottom Layer "VCCB_L06_P589" (solid, pour order 589): 135,126.25 135,155.75 135,225 223,225 cw(c223,223) 225,223 225,52.5 159,52.5 135,76.5
GND on Bottom Layer "GND_L06_P380" (solid, pour order 380): 199,44.75 199,48.25 202.5,48.25 202.5,44.75
OUT_B5 on Bottom Layer "OUT_B5_L06_P350" (solid, pour order 350): 198.75,52 225,52 225,77 198.75,77 196.75,75 196.75,54
GND on Bottom Layer "GND_L06_P543" (solid, pour order 543): 157,140.75 157,137.25 160.5,137.25 160.5,140.75
OUT_A6 on Bottom Layer "OUT_A6_L06_P522" (solid, pour order 522): 99.25,103 95.25,103 95.25,101.25 96,100.5 99.25,100.5
OUT_A7 on Bottom Layer "OUT_A7_L06_P519" (solid, pour order 519): 99.75,103 103.75,103 103.75,101.25 103,100.5 99.75,100.5
VCCA on Bottom Layer "VCCA_L06_P515" (solid, pour order 515): 103,100 103,96.75 96,96.75 96,100
OUT_A8 on Bottom Layer "OUT_A8_L06_P509" (solid, pour order 509): 114.25,103 110.25,103 110.25,101.25 111,100.5 114.25,100.5
OUT_A9 on Bottom Layer "OUT_A9_L06_P506" (solid, pour order 506): 114.75,103 118.75,103 118.75,101.25 118,100.5 114.75,100.5
VCCA on Bottom Layer "VCCA_L06_P502" (solid, pour order 502): 118,100 118,96.75 111,96.75 111,100
OUT_B6 on Bottom Layer "OUT_B6_L06_P496" (solid, pour order 496): 141.25,172 145.25,172 145.25,173.75 144.5,174.5 141.25,174.5
OUT_B7 on Bottom Layer "OUT_B7_L06_P493" (solid, pour order 493): 140.75,172 136.75,172 136.75,173.75 137.5,174.5 140.75,174.5
VCCB on Bottom Layer "VCCB_L06_P485" (solid, pour order 485): 137.5,175 137.5,178.25 144.5,178.25 144.5,175
OUT_B8 on Bottom Layer "OUT_B8_L06_P477" (solid, pour order 477): 126.25,172 130.25,172 130.25,173.75 129.5,174.5 126.25,174.5
OUT_B9 on Bottom Layer "OUT_B9_L06_P471" (solid, pour order 471): 125.75,172 121.75,172 121.75,173.75 122.5,174.5 125.75,174.5
VCCB on Bottom Layer "VCCB_L06_P467" (solid, pour order 467): 122.5,175 122.5,178.25 129.5,178.25 129.5,175
OUT_B13 on Bottom Layer "OUT_B13_L06_P463" (solid, pour order 463): 123,141 123,143.5 120.5,143.5 120.5,142 121.5,141
OUT_B11 on Bottom Layer "OUT_B11_L06_P456" (solid, pour order 456): 138,141 138,143.5 135.5,143.5 135.5,142 136.5,141
OUT_B10 on Bottom Layer "OUT_B10_L06_P451" (solid, pour order 451): 144,141 144,143.5 146.5,143.5 146.5,142 145.5,141
VCCB on Bottom Layer "VCCB_L06_P445" (solid, pour order 445): 139,139 139,143 143,143 143,139
VCCB on Bottom Layer "VCCB_L06_P440" (solid, pour order 440): 124,139 124,143 128,143 128,139
VCCA on Bottom Layer "VCCA_L06_P435" (solid, pour order 435): 105,134.25 105,138.25 109,138.25 109,134.25
GND on Bottom Layer "GND_L06_P430" (solid, pour order 430): 157,37.25 157,40.75 160.5,40.75 160.5,37.25
GND on Bottom Layer "GND_L06_P425" (solid, pour order 425): 85.75,35.5 85.75,39 89.25,39 89.25,35.5
GND on Bottom Layer "GND_L06_P420" (solid, pour order 420): 80.75,61.5 80.75,65 84.25,65 84.25,61.5
GND on Bottom Layer "GND_L06_P415" (solid, pour order 415): 76.5,79.5 76.5,83 80,83 80,79.5
GND on Bottom Layer "GND_L06_P410" (solid, pour order 410): 79,102 79,105.5 82.5,105.5 82.5,102
GND on Bottom Layer "GND_L06_P405" (solid, pour order 405): 77.75,126.25 77.75,129.75 81.25,129.75 81.25,126.25
GND on Bottom Layer "GND_L06_P400" (solid, pour order 400): 91,156.75 91,160.25 94.5,160.25 94.5,156.75
GND on Bottom Layer "GND_L06_P203" (solid, pour order 203): 92,192.75 92,196.25 95.5,196.25 95.5,192.75
GND on Bottom Layer "GND_L06_P395" (solid, pour order 395): 153.5,191 153.5,194.5 157,194.5 157,191
GND on Bottom Layer "GND_L06_P390" (solid, pour order 390): 160,162.5 160,166 163.5,166 163.5,162.5
GND on Bottom Layer "GND_L06_P385" (solid, pour order 385): 165.75,117 165.75,120.5 169.25,120.5 169.25,117
GND on Bottom Layer "GND_L06_P375" (solid, pour order 375): 165.75,65 165.75,68.5 169.25,68.5 169.25,65
GND on Bottom Layer "GND_L06_P370" (solid, pour order 370): 165.75,91 165.75,94.5 169.25,94.5 169.25,91
OUT_B2 on Bottom Layer "OUT_B2_L06_P259" (solid, pour order 259): 194,130.5 225,130.5 225,165.5 194,165.5
OUT_B1 on Bottom Layer "OUT_B1_L06_P238" (solid, pour order 238): 194,222.5 225,222.5 225,166.5 194,166.5
OUT_B12 on Bottom Layer "OUT_B12_L06_P206" (solid, pour order 206): 129,141 129,143.5 131.5,143.5 131.5,142 130.5,141
NetR43D_1 on Bottom Layer "NETR43D_1_L06_P331" (solid, pour order 331): 196,127 184.5,127 181.5,124 181.5,109 184.5,106 196,106
NetR43E_1 on Bottom Layer "NETR43E_1_L06_P343" (solid, pour order 343): 196,101 184.5,101 181.5,98 181.5,83 184.5,80 196,80
NetR43F_1 on Bottom Layer "NETR43F_1_L06_P365" (solid, pour order 365): 196,75 184.5,75 181.5,72 181.5,57 184.5,54 196,54
NetR82B_1 on Bottom Layer "NETR82B_1_L06_P237" (solid, pour order 237): 193,130.5 180.5,130.5 173,138 173,158 180.5,165.5 193,165.5
NetR43A_1 on Bottom Layer "NETR43A_1_L06_P260" (solid, pour order 260): 54,127.5 65.5,127.5 68.5,124.5 68.5,109.5 65.5,106.5 54,106.5
OUT_B4 on Bottom Layer "OUT_B4_L06_P338" (solid, pour order 338): 198.75,78 225,78 225,103 198.75,103 196.75,101 196.75,80
NetR43B_1 on Bottom Layer "NETR43B_1_L06_P307" (solid, pour order 307): 54.175,101.575 65.675,101.575 68.675,98.575 68.675,83.575 65.675,80.575 54.175,80.575
OUT_A4 on Bottom Layer "OUT_A4_L06_P302" (solid, pour order 302): 51.25,78.5 25,78.5 25,103.5 51.25,103.5 53.25,101.5 53.25,80.5
NetR43C_1 on Bottom Layer "NETR43C_1_L06_P319" (solid, pour order 319): 54,75.5 65.5,75.5 68.5,72.5 68.5,57.5 65.5,54.5 54,54.5
OUT_B3 on Bottom Layer "OUT_B3_L06_P326" (solid, pour order 326): 198.75,104 225,104 225,129 198.75,129 196.75,127 196.75,106
NetR82A_1 on Bottom Layer "NETR82A_1_L06_P248" (solid, pour order 248): 57,130.5 69.5,130.5 77,138 77,158 69.5,165.5 57,165.5
NetR60B_1 on Bottom Layer "NETR60B_1_L06_P225" (solid, pour order 225): 193,166.5 180.5,166.5 173,174 173,215 180.5,222.5 193,222.5
OUT_A5 on Bottom Layer "OUT_A5_L06_P314" (solid, pour order 314): 51.25,52.5 25,52.5 25,77.5 51.25,77.5 53.25,75.5 53.25,54.5
NetR60A_1 on Bottom Layer "NETR60A_1_L06_P240" (solid, pour order 240): 57,166.5 69.5,166.5 77,174 77,215 69.5,222.5 57,222.5
OUT_A1 on Bottom Layer "OUT_A1_L06_P239" (solid, pour order 239): 56,222.5 25,222.5 25,166.5 56,166.5
OUT_A3 on Bottom Layer "OUT_A3_L06_P207" (solid, pour order 207): 51.25,104.5 25,104.5 25,129.5 51.25,129.5 53.25,127.5 53.25,106.5
OUT_A2 on Bottom Layer "OUT_A2_L06_P253" (solid, pour order 253): 56,130.5 25,130.5 25,165.5 56,165.5

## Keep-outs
Keep-Out Layer:
  the board outline again, w0.5

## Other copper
Top Layer:
  pour cut-out: 166.25,33.25 166.25,40 170.25,40 170.25,33.25
  pour cut-out: 85.25,36.5 85.25,39.5 70.75,39.5 65,45.25 32,45.25 32,40.75 65,40.75 69.25,36.5
  pour cut-out: 158,48.5 158,43.75 158.75,43 161.25,43 161.25,48.5
Layer 1:
  region: 116.5,96.25 116.5,94 112.5,94 112.5,96.25
  region: 101.5,96.25 101.5,94 97.5,94 97.5,96.25
  region: 139,178.75 139,181 143,181 143,178.75
  region: 124,178.75 124,181 128,181 128,178.75
  pour cut-out: 35.5,45.25 35.5,40.75 59.25,40.75 59.25,45.25
  pour cut-out: 155.75,48.5 155.75,43 161.25,43 161.25,48.5
Layer 2:
  region: 116.5,96.25 116.5,94 112.5,94 112.5,96.25
  region: 101.5,96.25 101.5,94 97.5,94 97.5,96.25
  region: 139,178.75 139,181 143,181 143,178.75
  region: 124,178.75 124,181 128,181 128,178.75
  pour cut-out: 35.5,45.25 35.5,40.75 59.25,40.75 59.25,45.25
  pour cut-out: 155.75,48.5 155.75,43 161.25,43 161.25,48.5
Layer 3:
  region: 116.5,96.25 116.5,94 112.5,94 112.5,96.25
  region: 101.5,96.25 101.5,94 97.5,94 97.5,96.25
  region: 139,178.75 139,181 143,181 143,178.75
  region: 124,178.75 124,181 128,181 128,178.75
  pour cut-out: 35.5,45.25 35.5,40.75 59.25,40.75 59.25,45.25
  pour cut-out: 155.75,48.5 155.75,43 161.25,43 161.25,48.5
Layer 4:
  region: 116.5,96.25 116.5,94 112.5,94 112.5,96.25
  region: 101.5,96.25 101.5,94 97.5,94 97.5,96.25
  region: 139,178.75 139,181 143,181 143,178.75
  region: 124,178.75 124,181 128,181 128,178.75
  pour cut-out: 35.5,45.25 35.5,40.75 59.25,40.75 59.25,45.25
  pour cut-out: 155.75,48.5 155.75,43 161.25,43 161.25,48.5
Bottom Layer:
  region: 116.5,96.25 116.5,94 112.5,94 112.5,96.25
  region: 101.5,96.25 101.5,94 97.5,94 97.5,96.25
  region: 139,178.75 139,181 143,181 143,178.75
  region: 124,178.75 124,181 128,181 128,178.75
  pour cut-out: 35.5,45.25 35.5,40.75 59.25,40.75 59.25,45.25
  pour cut-out: 155.75,48.5 155.75,43 161.25,43 161.25,48.5
Multi-Layer:
  pour cut-out: 139.5,66.5 143,66.5 143,62.5 139.5,62.5
  pour cut-out: 85.5,47.25 89,47.25 89,43.25 85.5,43.25

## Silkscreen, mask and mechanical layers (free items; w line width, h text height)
Top Overlay:
  drawing of 52 lines, arcs and shapes, not listed
  text "VCC_EXT" at 110.252,222.875 h1.5
  text "GND" at 133.001,222.75 h1.5
  text "VCCB" at 170.001,214.25 h1.5
  text "VCCA" at 74.751,214 h1.5
  text "OUT_A1" at 65.751,202.875 h1.5
  text "OUT_B1" at 175.751,202.875 h1.5
  text "VCCB" at 127.059,198.175 h0.65
  text "VCCA" at 118.559,197.925 h0.65
  text "SPI5" at 138.563,193.731 h0.65
  text "SPI9" at 104.273,177.983 h0.65
  text "OUT_B9" at 119.984,168.917 h0.8
  text "OUT_B8" at 127.484,168.917 h0.8
  text "OUT_B7" at 134.984,168.917 h0.8
  text "OUT_B6" at 142.484,168.917 h0.8
  text "OUT_A2" at 65.501,154.625 h1.5
  text "OUT_B2" at 175.501,154.375 h1.5
  text "OUT_B13" at 119.651,147.417 h0.8
  text "OUT_B12" at 127.151,147.417 h0.8
  text "OUT_B11" at 134.784,147.417 h0.8
  text "OUT_B10" at 142.151,147.417 h0.8
  text "OUT_A13" at 115.662,126.902 h0.8
  text "OUT_A10" at 93.151,126.667 h0.8
  text "OUT_A11" at 100.784,126.667 h0.8
  text "OUT_A12" at 108.151,126.667 h0.8
  text "OUT_A3" at 60.001,123.625 h1.5
  text "OUT_B3" at 181.501,122.625 h1.5
  text "OUT_A6" at 93.496,105.402 h0.8
  text "OUT_A7" at 100.996,105.402 h0.8
  text "OUT_A8" at 108.496,105.402 h0.8
  text "OUT_A9" at 115.996,105.402 h0.8
  text "SPI2" at 157.867,101.529 h0.65
  text "JTAG" at 130.165,101.295 h0.8 r90
  text "OUT_A4" at 60.001,96.875 h1.5
  text "OUT_B4" at 181.501,96.875 h1.5
  text "SPI0" at 101.863,82.175 h0.65
  text "OUT_A5" at 60.001,71.625 h1.5
  text "OUT_B5" at 181.501,70.875 h1.5
  text "NORMAL" at 175.909,51.925 h0.65
  text "DBUG" at 181.809,51.925 h0.65
  text "ETHERNET" at 36.184,46.6 h0.8
  text "SPI3 / CS0" at 186.213,43.455 h0.65
  text "3V3_STB" at 207.584,41.729 h0.65
  text "3V3" at 191.434,35.1 h0.8
  text "5V" at 194.084,35.1 h0.8
  text "ST GENERIC PDU" at 47.128,34.268 h2
  text "SPI3" at 163.709,31.933 h0.65
  text "rev 2.3 (06/2025) / EMEA ADG MA PA-A" at 52.5,31.531 h1
  text "CAN" at 187.402,29.572 h0.8
  text "UART" at 99.026,29.35 h0.8
  text "BOOTLOADER" at 122.859,27.925 h0.65
  text "101" at 61.155,27.194 h1
Top Paste:
  drawing of 704 lines, arcs and shapes, not listed
Bottom Solder:
  drawing of 71 lines, arcs and shapes, not listed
